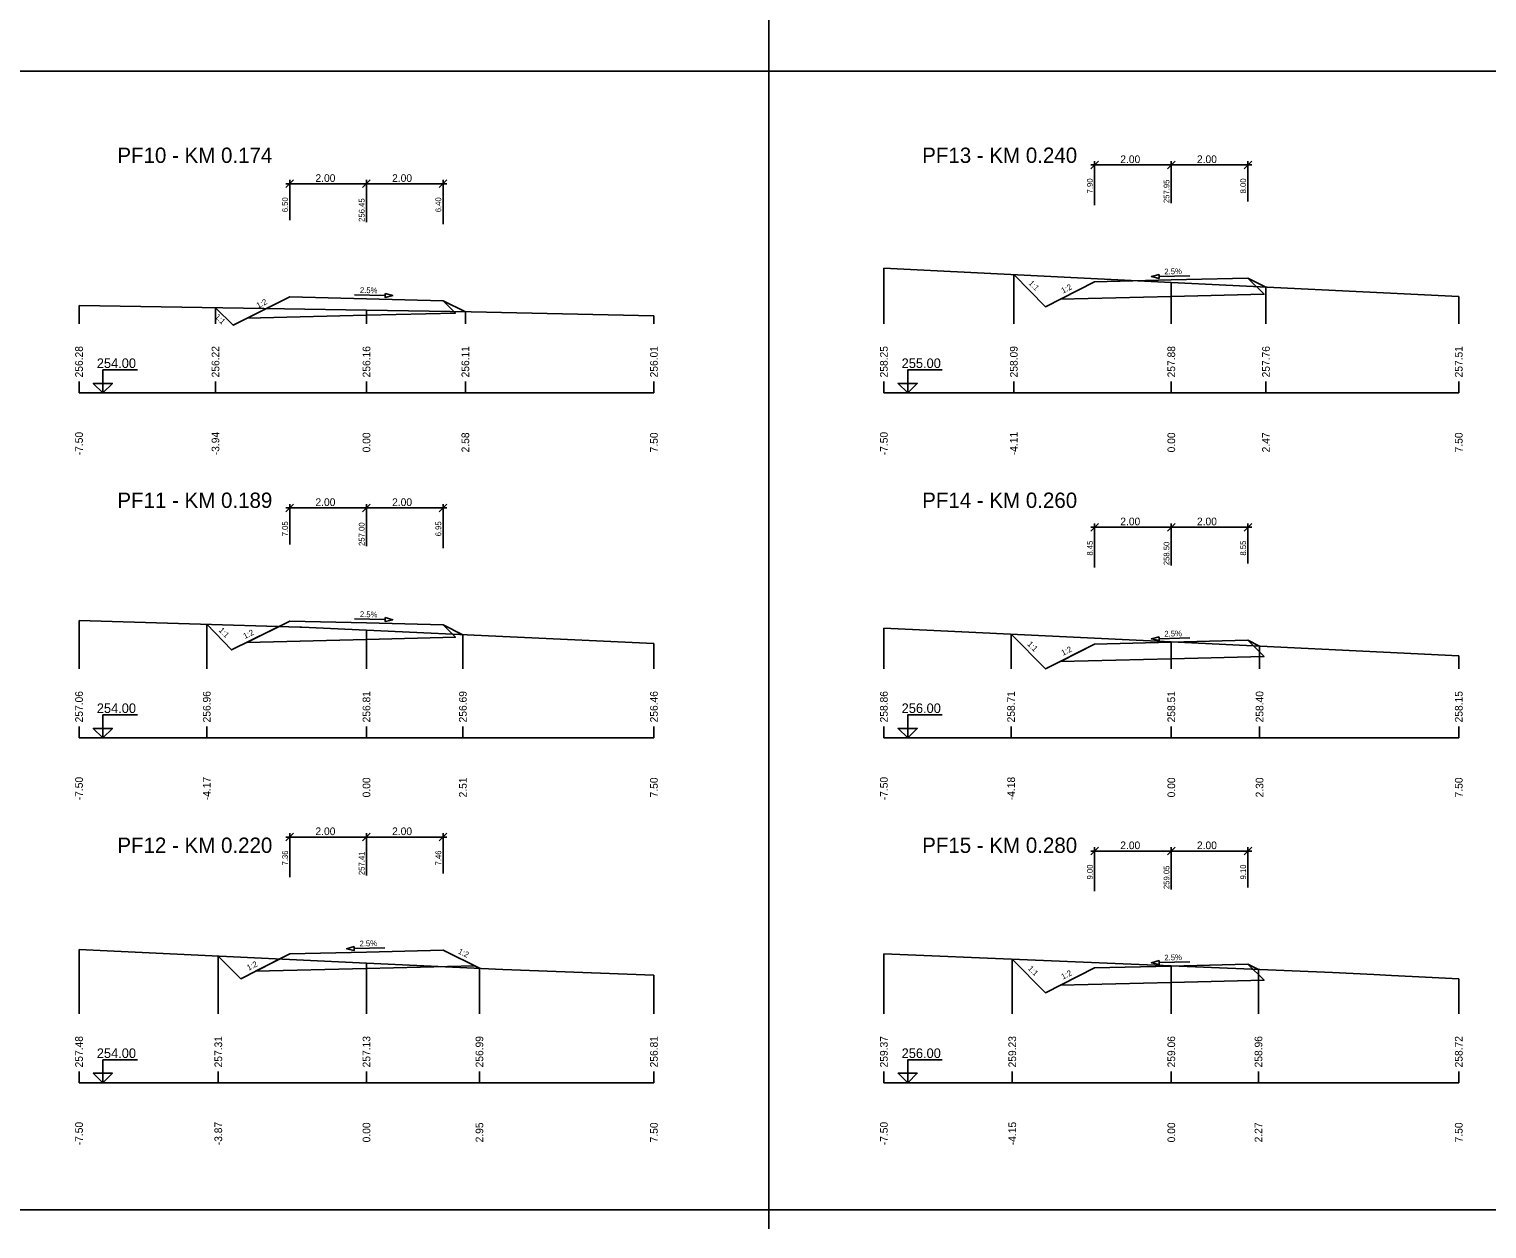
# Model space of a CAD drawing. Extents: x -1895 to 2525, y -19 to 585.
# Drawn here: x -1243 to -862.6, y -19.1 to 293.9 of the extents above; entities that cross this region are included whole.
import ezdxf

# ---------------------------------------------------------------- set-up
doc = ezdxf.new("R2010")
doc.units = 0
for name, color, linetype in [('KOTA', 7, 'Continuous'), ('KOTA_DELKY', 7, 'Continuous'), ('KOTA_DELKY_CONT', 7, 'Continuous'), ('NS_TELESO_VOZOVKY', 7, 'Continuous'), ('NS_V_PF', 7, 'Continuous'), ('REZY_PF_PUVODNI', 7, 'Continuous'), ('SESTAVY_REZU_PF', 7, 'Continuous'), ('SKLON', 7, 'Continuous'), ('SVK', 7, 'Continuous')]:
    doc.layers.add(name, color=color, linetype=linetype)

msp = doc.modelspace()

# ---------------------------------------------------------------- linework, layer by layer
for p, q in [((-1049.95, 287.93), (-1049.95, 277.93)), ((-1049.95, 287.93), (-1049.95, 277.93)), ((-1049.95, 287.93), (-1049.95, 277.93)), ((-1049.95, 287.93), (-1049.95, 277.93)), ((-1044.95, 282.93), (-1054.95, 282.93)), ((-1044.95, 282.93), (-1054.95, 282.93)), ((-1044.95, 282.93), (-1054.95, 282.93)), ((-1044.95, 282.93), (-1054.95, 282.93)), ((-1049.95, -9.07), (-1049.95, -19.07)), ((-1049.95, -9.07), (-1049.95, -19.07)), ((-1044.95, -14.07), (-1054.95, -14.07)), ((-1044.95, -14.07), (-1054.95, -14.07))]:
    msp.add_line(p, q)
for points in [[(-1259.95, 579.93), (-1049.95, 579.93), (-1049.95, 282.93), (-1259.95, 282.93)], [(-1049.95, 579.93), (-839.95, 579.93), (-839.95, 282.93), (-1049.95, 282.93)], [(-1259.95, 282.93), (-1049.95, 282.93), (-1049.95, -14.07), (-1259.95, -14.07)], [(-1049.95, 282.93), (-839.95, 282.93), (-839.95, -14.07), (-1049.95, -14.07)]]:
    msp.add_lwpolyline(points, close=True)
at = {"layer": 'KOTA'}
for points in [[(-1223.73, 201.5), (-1226.23, 201.5), (-1223.73, 199), (-1223.73, 205), (-1214.73, 205)], [(-1013.73, 201.5), (-1016.23, 201.5), (-1013.73, 199), (-1013.73, 205), (-1004.73, 205)], [(-1223.73, 199), (-1221.23, 201.5), (-1223.73, 201.5)], [(-1013.73, 199), (-1011.23, 201.5), (-1013.73, 201.5)], [(-1223.73, 111.5), (-1226.23, 111.5), (-1223.73, 109), (-1223.73, 115), (-1214.73, 115)], [(-1013.73, 111.5), (-1016.23, 111.5), (-1013.73, 109), (-1013.73, 115), (-1004.73, 115)], [(-1223.73, 109), (-1221.23, 111.5), (-1223.73, 111.5)], [(-1013.73, 109), (-1011.23, 111.5), (-1013.73, 111.5)], [(-1223.73, 21.5), (-1226.23, 21.5), (-1223.73, 19), (-1223.73, 25), (-1214.73, 25)], [(-1013.73, 21.5), (-1016.23, 21.5), (-1013.73, 19), (-1013.73, 25), (-1004.73, 25)], [(-1223.73, 19), (-1221.23, 21.5), (-1223.73, 21.5)], [(-1013.73, 19), (-1011.23, 21.5), (-1013.73, 21.5)]]:
    msp.add_lwpolyline(points, dxfattribs=at)
at = {"layer": 'KOTA_DELKY'}
for points in [[(-965.95, 257.46), (-963.95, 259.46)], [(-964.95, 247.96), (-964.95, 259.46)], [(-945.95, 257.46), (-943.95, 259.46)], [(-945.95, 257.46), (-943.95, 259.46)], [(-944.95, 248.46), (-944.95, 259.46)], [(-944.95, 248.46), (-944.95, 259.46)], [(-925.95, 257.46), (-923.95, 259.46)], [(-924.95, 248.96), (-924.95, 259.46)], [(-965.95, 258.46), (-943.95, 258.46)], [(-945.95, 258.46), (-923.95, 258.46)], [(-1175.95, 252.55), (-1173.95, 254.55)], [(-1175.95, 253.55), (-1153.95, 253.55)], [(-1174.95, 244.05), (-1174.95, 254.55)], [(-1155.95, 252.55), (-1153.95, 254.55)], [(-1155.95, 252.55), (-1153.95, 254.55)], [(-1155.95, 253.55), (-1133.95, 253.55)], [(-1154.95, 243.55), (-1154.95, 254.55)], [(-1154.95, 243.55), (-1154.95, 254.55)], [(-1135.95, 252.55), (-1133.95, 254.55)], [(-1134.95, 243.05), (-1134.95, 254.55)], [(-1175.95, 168), (-1173.95, 170)], [(-1175.95, 169), (-1153.95, 169)], [(-1174.95, 159.5), (-1174.95, 170)], [(-1155.95, 168), (-1153.95, 170)], [(-1155.95, 168), (-1153.95, 170)], [(-1155.95, 169), (-1133.95, 169)], [(-1154.95, 159), (-1154.95, 170)], [(-1154.95, 159), (-1154.95, 170)], [(-1135.95, 168), (-1133.95, 170)], [(-1134.95, 158.5), (-1134.95, 170)], [(-965.95, 162.97), (-963.95, 164.97)], [(-965.95, 163.97), (-943.95, 163.97)], [(-964.95, 153.47), (-964.95, 164.97)], [(-945.95, 162.97), (-943.95, 164.97)], [(-945.95, 162.97), (-943.95, 164.97)], [(-945.95, 163.97), (-923.95, 163.97)], [(-944.95, 153.97), (-944.95, 164.97)], [(-944.95, 153.97), (-944.95, 164.97)], [(-925.95, 162.97), (-923.95, 164.97)], [(-924.95, 154.47), (-924.95, 164.97)], [(-1175.95, 82.14), (-1173.95, 84.14)], [(-1174.95, 72.64), (-1174.95, 84.14)], [(-1155.95, 82.14), (-1153.95, 84.14)], [(-1155.95, 82.14), (-1153.95, 84.14)], [(-1154.95, 73.14), (-1154.95, 84.14)], [(-1154.95, 73.14), (-1154.95, 84.14)], [(-1135.95, 82.14), (-1133.95, 84.14)], [(-1134.95, 73.64), (-1134.95, 84.14)], [(-1175.95, 83.14), (-1153.95, 83.14)], [(-1155.95, 83.14), (-1133.95, 83.14)], [(-965.95, 78.48), (-963.95, 80.48)], [(-964.95, 68.98), (-964.95, 80.48)], [(-945.95, 78.48), (-943.95, 80.48)], [(-945.95, 78.48), (-943.95, 80.48)], [(-944.95, 69.48), (-944.95, 80.48)], [(-944.95, 69.48), (-944.95, 80.48)], [(-925.95, 78.48), (-923.95, 80.48)], [(-924.95, 69.98), (-924.95, 80.48)], [(-965.95, 79.48), (-943.95, 79.48)], [(-945.95, 79.48), (-923.95, 79.48)]]:
    msp.add_lwpolyline(points, dxfattribs=at)
at = {"layer": 'NS_TELESO_VOZOVKY'}
for points in [[(-944.95, 228.46), (-924.95, 228.96), (-924.95, 228.96), (-920.75, 224.76), (-944.95, 224.16), (-973.89, 223.43), (-964.95, 227.96), (-964.95, 227.96), (-944.95, 228.46)], [(-1154.95, 223.55), (-1134.95, 223.05), (-1134.95, 223.05), (-1131.73, 219.83), (-1154.95, 219.25), (-1186.05, 218.47), (-1174.95, 224.05), (-1174.95, 224.05), (-1154.95, 223.55)], [(-1154.95, 139), (-1134.95, 138.5), (-1134.95, 138.5), (-1131.73, 135.28), (-1154.95, 134.7), (-1186.18, 133.92), (-1174.95, 139.5), (-1174.95, 139.5), (-1154.95, 139)], [(-944.95, 133.97), (-924.95, 134.47), (-924.95, 134.47), (-920.75, 130.27), (-944.95, 129.67), (-973.89, 128.95), (-964.95, 133.47), (-964.95, 133.47), (-944.95, 133.97)], [(-1154.95, 53.14), (-1134.95, 53.64), (-1134.95, 53.64), (-1125.48, 48.9), (-1126.76, 49.55), (-1154.95, 48.84), (-1183.89, 48.12), (-1174.95, 52.64), (-1174.95, 52.64), (-1154.95, 53.14)], [(-944.95, 49.48), (-924.95, 49.98), (-924.95, 49.98), (-920.75, 45.79), (-944.95, 45.18), (-973.89, 44.46), (-964.95, 48.98), (-964.95, 48.98), (-944.95, 49.48)]]:
    msp.add_lwpolyline(points, dxfattribs=at)
at = {"layer": 'NS_V_PF'}
for points in [[(-986.05, 229.86), (-977.76, 221.48), (-964.95, 227.96), (-964.95, 227.96), (-944.95, 228.46), (-924.95, 228.96), (-924.95, 228.96), (-920.25, 226.61)], [(-1194.35, 221.22), (-1189.7, 216.64), (-1174.95, 224.05), (-1174.95, 224.05), (-1154.95, 223.55), (-1134.95, 223.05), (-1134.95, 223.05), (-1129.15, 220.15)], [(-1196.62, 138.64), (-1190.14, 131.95), (-1174.95, 139.5), (-1174.95, 139.5), (-1154.95, 139), (-1134.95, 138.5), (-1134.95, 138.5), (-1129.8, 135.93)], [(-986.75, 136.08), (-977.76, 126.99), (-964.95, 133.47), (-964.95, 133.47), (-944.95, 133.97), (-924.95, 134.47), (-924.95, 134.47), (-921.92, 132.95)], [(-1193.61, 52.08), (-1187.76, 46.16), (-1174.95, 52.64), (-1174.95, 52.64), (-1154.95, 53.14), (-1134.95, 53.64), (-1134.95, 53.64), (-1125.48, 48.9)], [(-986.45, 51.29), (-977.76, 42.51), (-964.95, 48.98), (-964.95, 48.98), (-944.95, 49.48), (-924.95, 49.98), (-924.95, 49.98), (-922.21, 48.61)]]:
    msp.add_lwpolyline(points, dxfattribs=at)
at = {"layer": 'REZY_PF_PUVODNI'}
for points in [[(-1019.95, 231.54), (-944.95, 227.83), (-869.95, 224.12)], [(-1229.95, 221.8), (-1154.95, 220.57), (-1127.67, 220.12), (-1079.95, 219.09)], [(-1229.95, 139.62), (-1172.3, 137.92), (-1171.8, 137.9), (-1154.95, 137.11), (-1079.95, 133.59)], [(-1019.95, 137.59), (-1006.88, 137.05), (-944.95, 134.06), (-869.95, 130.45)], [(-1229.95, 53.78), (-1154.95, 50.28), (-1119.36, 48.62), (-1079.95, 47.08)], [(-1019.95, 52.68), (-944.95, 49.56), (-902.87, 47.81), (-892.13, 47.32), (-887.48, 46.99), (-882.14, 46.78), (-869.95, 46.16)]]:
    msp.add_lwpolyline(points, dxfattribs=at)
at = {"layer": 'SESTAVY_REZU_PF'}
for points in [[(-1229.95, 199), (-1079.95, 199)], [(-1019.95, 199), (-869.95, 199)], [(-1229.95, 109), (-1079.95, 109)], [(-1019.95, 109), (-869.95, 109)], [(-1229.95, 19), (-1079.95, 19)], [(-1019.95, 19), (-869.95, 19)]]:
    msp.add_lwpolyline(points, dxfattribs=at)
at = {"layer": 'SKLON'}
for points in [[(-948.16, 229.88), (-950.15, 229.33), (-948.14, 228.88), (-948.16, 229.88)], [(-948.15, 229.38), (-940.15, 229.58)], [(-1158.1, 224.63), (-1150.1, 224.43)], [(-1150.09, 224.93), (-1148.1, 224.38), (-1150.11, 223.93), (-1150.09, 224.93)], [(-1158.1, 140.08), (-1150.1, 139.88)], [(-1150.09, 140.38), (-1148.1, 139.83), (-1150.11, 139.38), (-1150.09, 140.38)], [(-948.16, 135.39), (-950.15, 134.84), (-948.14, 134.39), (-948.16, 135.39)], [(-948.15, 134.89), (-940.15, 135.09)], [(-1158.16, 54.56), (-1160.15, 54.01), (-1158.14, 53.56), (-1158.16, 54.56)], [(-1158.15, 54.06), (-1150.15, 54.26)], [(-948.16, 50.9), (-950.15, 50.35), (-948.14, 49.9), (-948.16, 50.9)], [(-948.15, 50.4), (-940.15, 50.6)]]:
    msp.add_lwpolyline(points, dxfattribs=at)
at = {"layer": 'SVK'}
for points in [[(-1019.95, 217), (-1019.95, 231.54)], [(-986.05, 217), (-986.05, 229.86)], [(-944.95, 217), (-944.95, 227.83)], [(-920.25, 217), (-920.25, 226.61)], [(-1229.95, 217), (-1229.95, 221.8)], [(-1194.35, 217), (-1194.35, 221.22)], [(-869.95, 217), (-869.95, 224.12)], [(-1154.95, 217), (-1154.95, 220.57)], [(-1129.15, 217), (-1129.15, 220.15)], [(-1079.95, 217), (-1079.95, 219.09)], [(-1229.95, 199), (-1229.95, 202)], [(-1194.35, 199), (-1194.35, 202)], [(-1154.95, 199), (-1154.95, 202)], [(-1129.15, 199), (-1129.15, 202)], [(-1079.95, 199), (-1079.95, 202)], [(-1019.95, 199), (-1019.95, 202)], [(-986.05, 199), (-986.05, 202)], [(-944.95, 199), (-944.95, 202)], [(-920.25, 199), (-920.25, 202)], [(-869.95, 199), (-869.95, 202)], [(-1229.95, 127), (-1229.95, 139.62)], [(-1196.62, 127), (-1196.62, 138.64)], [(-1154.95, 127), (-1154.95, 137.11)], [(-1019.95, 127), (-1019.95, 137.59)], [(-1129.8, 127), (-1129.8, 135.93)], [(-1079.95, 127), (-1079.95, 133.59)], [(-986.75, 127), (-986.75, 136.08)], [(-944.95, 127), (-944.95, 134.06)], [(-921.92, 127), (-921.92, 132.95)], [(-869.95, 127), (-869.95, 130.45)], [(-1229.95, 109), (-1229.95, 112)], [(-1196.62, 109), (-1196.62, 112)], [(-1154.95, 109), (-1154.95, 112)], [(-1129.8, 109), (-1129.8, 112)], [(-1079.95, 109), (-1079.95, 112)], [(-1019.95, 109), (-1019.95, 112)], [(-986.75, 109), (-986.75, 112)], [(-944.95, 109), (-944.95, 112)], [(-921.92, 109), (-921.92, 112)], [(-869.95, 109), (-869.95, 112)], [(-1229.95, 37), (-1229.95, 53.78)], [(-1193.61, 37), (-1193.61, 52.08)], [(-1154.95, 37), (-1154.95, 50.28)], [(-1019.95, 37), (-1019.95, 52.68)], [(-986.45, 37), (-986.45, 51.29)], [(-944.95, 37), (-944.95, 49.56)], [(-1125.48, 37), (-1125.48, 48.9)], [(-1079.95, 37), (-1079.95, 47.08)], [(-922.21, 37), (-922.21, 48.61)], [(-869.95, 37), (-869.95, 46.16)], [(-1229.95, 19), (-1229.95, 22)], [(-1193.61, 19), (-1193.61, 22)], [(-1154.95, 19), (-1154.95, 22)], [(-1125.48, 19), (-1125.48, 22)], [(-1079.95, 19), (-1079.95, 22)], [(-1019.95, 19), (-1019.95, 22)], [(-986.45, 19), (-986.45, 22)], [(-944.95, 19), (-944.95, 22)], [(-922.21, 19), (-922.21, 22)], [(-869.95, 19), (-869.95, 22)]]:
    msp.add_lwpolyline(points, dxfattribs=at)

# ---------------------------------------------------------------- texts
at = {"layer": 'KOTA'}
for s, p in [('254.00', (-1225.31, 205.5)), ('255.00', (-1015.31, 205.5)), ('254.00', (-1225.31, 115.5)), ('256.00', (-1015.31, 115.5)), ('254.00', (-1225.31, 25.5)), ('256.00', (-1015.31, 25.5))]:
    msp.add_text(s, height=2.5, dxfattribs=at).set_placement(p)
at = {"layer": 'KOTA_DELKY'}
for p in [(-958.26, 258.96), (-938.26, 258.96), (-1168.26, 254.05), (-1148.26, 254.05), (-1168.26, 169.5), (-1148.26, 169.5), (-958.26, 164.47), (-938.26, 164.47), (-1168.26, 83.64), (-1148.26, 83.64), (-958.26, 79.98), (-938.26, 79.98)]:
    msp.add_text('2.00', height=2, dxfattribs=at).set_placement(p)
at = {"layer": 'KOTA_DELKY_CONT'}
for s, p in [('7.90', (-965.45, 251.05)), ('8.00', (-925.45, 251.05)), ('257.95', (-945.45, 248.53)), ('6.50', (-1175.45, 246.14)), ('256.45', (-1155.45, 243.62)), ('6.40', (-1135.45, 246.14)), ('7.05', (-1175.45, 161.59)), ('257.00', (-1155.45, 159.08)), ('6.95', (-1135.45, 161.59)), ('8.45', (-965.45, 156.56)), ('258.50', (-945.45, 154.05)), ('8.55', (-925.45, 156.56)), ('7.36', (-1175.45, 75.73)), ('257.41', (-1155.45, 73.22)), ('7.46', (-1135.45, 75.73)), ('9.00', (-965.45, 72.07)), ('259.05', (-945.45, 69.56)), ('9.10', (-925.45, 72.07))]:
    msp.add_text(s, height=1.5, rotation=90, dxfattribs=at).set_placement(p)
at = {"layer": 'SESTAVY_REZU_PF'}
for s, p in [('PF10 - KM 0.174', (-1219.95, 259)), ('PF13 - KM 0.240', (-1009.95, 259)), ('PF11 - KM 0.189', (-1219.95, 169)), ('PF14 - KM 0.260', (-1009.95, 169)), ('PF12 - KM 0.220', (-1219.95, 79)), ('PF15 - KM 0.280', (-1009.95, 79))]:
    msp.add_text(s, height=4, dxfattribs=at).set_placement(p)
at = {"layer": 'SKLON'}
for s, rotation, p in [('1:1', 314.7121, (-982.3, 227.49)), ('2.5%', 1.4321, (-946.75, 229.91)), ('2.5%', 358.5679, (-1156.68, 225.09)), ('1:2', 26.8233, (-973.21, 224.9)), ('1:2', 26.6688, (-1183.21, 221.02)), ('1:1', 315.4346, (-1194.63, 218.73)), ('2.5%', 358.5679, (-1156.68, 140.54)), ('1:1', 314.1179, (-1193.6, 136.95)), ('1:2', 26.4309, (-1186.66, 134.79)), ('2.5%', 1.4321, (-946.75, 135.42)), ('1:1', 314.7121, (-982.65, 133.36)), ('1:2', 26.8233, (-973.21, 130.41)), ('2.5%', 1.4321, (-1156.75, 54.6)), ('1:2', 333.4349, (-1131.18, 52.87)), ('1:2', 26.8233, (-1185.71, 48.26)), ('1:1', 314.7121, (-982.5, 48.72)), ('2.5%', 1.4321, (-946.75, 50.94)), ('1:2', 26.8233, (-973.21, 45.92))]:
    msp.add_text(s, height=1.5, rotation=rotation, dxfattribs=at).set_placement(p)
at = {"layer": 'SVK'}
for s, p in [(' 256.28', (-1228.95, 202.3)), (' 256.22', (-1193.35, 202.3)), (' 256.16', (-1153.95, 202.3)), (' 256.11', (-1128.15, 202.3)), (' 256.01', (-1078.95, 202.3)), (' 258.25', (-1018.95, 202.3)), (' 258.09', (-985.05, 202.3)), (' 257.88', (-943.95, 202.3)), (' 257.76', (-919.25, 202.3)), (' 257.51', (-868.95, 202.3)), (' -7.50', (-1228.95, 182)), (' -3.94', (-1193.35, 182)), ('  0.00', (-1153.95, 182)), ('  2.58', (-1128.15, 182)), ('  7.50', (-1078.95, 182)), (' -7.50', (-1018.95, 182)), (' -4.11', (-985.05, 182)), ('  0.00', (-943.95, 182)), ('  2.47', (-919.25, 182)), ('  7.50', (-868.95, 182)), (' 257.06', (-1228.95, 112.3)), (' 256.96', (-1195.62, 112.3)), (' 256.81', (-1153.95, 112.3)), (' 256.69', (-1128.8, 112.3)), (' 256.46', (-1078.95, 112.3)), (' 258.86', (-1018.95, 112.3)), (' 258.71', (-985.75, 112.3)), (' 258.51', (-943.95, 112.3)), (' 258.40', (-920.92, 112.3)), (' 258.15', (-868.95, 112.3)), (' -7.50', (-1228.95, 92)), (' -4.17', (-1195.62, 92)), ('  0.00', (-1153.95, 92)), ('  2.51', (-1128.8, 92)), ('  7.50', (-1078.95, 92)), (' -7.50', (-1018.95, 92)), (' -4.18', (-985.75, 92)), ('  0.00', (-943.95, 92)), ('  2.30', (-920.92, 92)), ('  7.50', (-868.95, 92)), (' 257.48', (-1228.95, 22.3)), (' 257.31', (-1192.61, 22.3)), (' 257.13', (-1153.95, 22.3)), (' 256.99', (-1124.48, 22.3)), (' 256.81', (-1078.95, 22.3)), (' 259.37', (-1018.95, 22.3)), (' 259.23', (-985.45, 22.3)), (' 259.06', (-943.95, 22.3)), (' 258.96', (-921.21, 22.3)), (' 258.72', (-868.95, 22.3)), (' -7.50', (-1228.95, 2)), (' -3.87', (-1192.61, 2)), ('  0.00', (-1153.95, 2)), ('  2.95', (-1124.48, 2)), ('  7.50', (-1078.95, 2)), (' -7.50', (-1018.95, 2)), (' -4.15', (-985.45, 2)), ('  0.00', (-943.95, 2)), ('  2.27', (-921.21, 2)), ('  7.50', (-868.95, 2))]:
    msp.add_text(s, height=2, rotation=90, dxfattribs=at).set_placement(p)

doc.saveas('drawing.dxf')
